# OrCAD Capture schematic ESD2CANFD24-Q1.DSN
size A
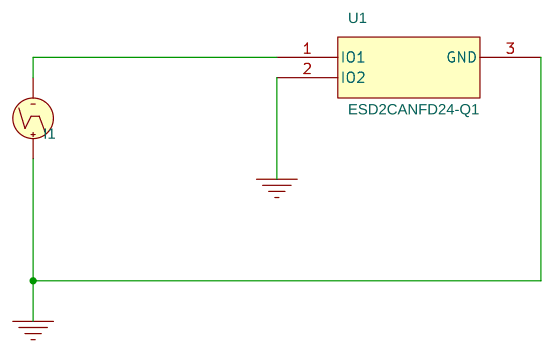
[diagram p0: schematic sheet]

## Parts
I1  IPWL_GENERIC
U1  ESD2CANFD24-Q1

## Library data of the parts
I1 = IPWL_GENERIC: AppProp: No_reps$POINTS_TYPE_PWL$0$0; FIRST_NPAIRS: 0n 0 0.8n 30 6n 8 9.5n 12.5 10n 13 18n 16 22n 16 25n 16 60n 9 72n 7 82n 5.3 150n 0; PSpiceTemplate: I^@REFDES %+ %- ?DC|DC @DC| ?AC|AC @AC| PWL ?TSF|TIME_SCALE_FACTOR=@TSF| ?VSF|VALUE_SCALE_FACTOR=@VSF| ?REPEAT_VALUE| \n+ REPEAT FOR @REPEAT_VALUE| \n+ @FIRST_NPAIRS ?SECOND_NPAIRS|\n+ @SECOND_NPAIRS ?THIRD_NPAIRS/\n+ @THIRD_NPAIRS/| ?REPEAT_VALUE| \n+ ENDREPEAT|
U1 = ESD2CANFD24-Q1

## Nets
0: I1.1(+) U1.2(IO2) U1.3(GND)
N01697: I1.2(-) U1.1(IO1)
